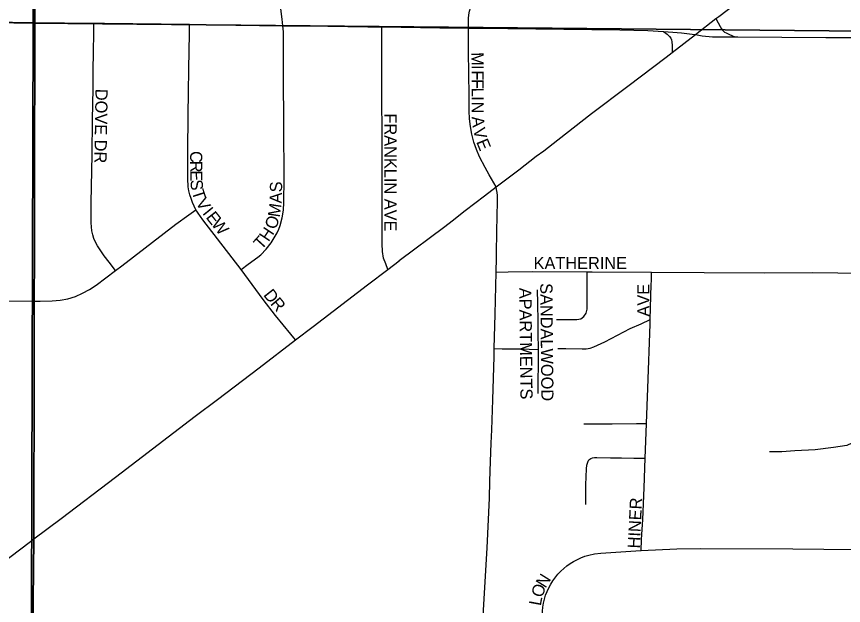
# Model space of a CAD drawing. Extents: x 1874609 to 2204689, y 815661 to 1281160.
# Drawn here: x 2012825 to 2016212, y 1038772 to 1041183 of the extents above; entities that cross this region are included whole.
import ezdxf

# ---------------------------------------------------------------- set-up
doc = ezdxf.new("R2010")
doc.units = 0
for name, color, linetype in [('GM_X_City_Street', 7, 'Continuous'), ('GM_X_City_Street_Text', 7, 'Continuous'), ('GM_X_Minor_River', 7, 'Continuous'), ('GM_X_Section', 7, 'Continuous'), ('GM_X_Township', 7, 'Continuous')]:
    doc.layers.add(name, color=color, linetype=linetype)

msp = doc.modelspace()

# ---------------------------------------------------------------- linework, layer by layer
at = {"layer": 'GM_X_City_Street'}
for points in [[(2013915.2, 1041145.8), (2013912.5, 1041172.4), (2013904.1, 1041237), (2013902.3, 1041253.9), (2013901.2, 1041272.7), (2013899.5, 1041318.9), (2013899.8, 1041467.4), (2013898.3, 1041608.2), (2013900.7, 1041634.7), (2013900.1, 1041657.5), (2013904.2, 1041695), (2013907.4, 1041727.9), (2013912.9, 1041760.4), (2013932, 1041840.3), (2013995.2, 1042077.5), (2014035.6, 1042236.1), (2014053.9, 1042301.5)], [(2014676.5, 1041135.7), (2014676.5, 1041175.8), (2014677.3, 1041190.8), (2014679.7, 1041204.9), (2014684.5, 1041219.1), (2014690.3, 1041233.7), (2014697.3, 1041247), (2014706, 1041259.7), (2014715.3, 1041273), (2014734.2, 1041299.5), (2014784.1, 1041364.7), (2014813.4, 1041404.4), (2014832.4, 1041430.6), (2014842.2, 1041443.4), (2014851.7, 1041456.1), (2014860, 1041468.7), (2014862.6, 1041474.3)], [(2015689.7, 1041174.7), (2015701.2, 1041183.5), (2016027.1, 1041431.9), (2016096.6, 1041485.7)], [(2012727.6, 1041161.3), (2012808.4, 1041160.3), (2012899.1, 1041159.1), (2012902.8, 1041159.1)], [(2012902.8, 1041159.1), (2013141.6, 1041156.1)], [(2013230.2, 1040143.5), (2013204, 1040178), (2013184.1, 1040204.2), (2013156.3, 1040244.8), (2013148, 1040259), (2013141.4, 1040274.1), (2013136.6, 1040289.8), (2013133.3, 1040305.9), (2013130.3, 1040338.7), (2013130, 1040371.5), (2013130.1, 1040420.9), (2013134.2, 1040618.4), (2013136.2, 1040759.9), (2013137.9, 1040888.3), (2013138.9, 1040958.7), (2013140, 1041041.5), (2013141, 1041111.8), (2013141.6, 1041156.1)], [(2013141.6, 1041156.1), (2013185.2, 1041155.5), (2013533.2, 1041151.5)], [(2015606.3, 1041110.1), (2015689.7, 1041174.7)], [(2015689.7, 1041174.7), (2015698.5, 1041158), (2015706.7, 1041142.6), (2015712.2, 1041133.4), (2015718.1, 1041126.6), (2015725.3, 1041119.8), (2015731.1, 1041115.9), (2015745.5, 1041109.3), (2015766.9, 1041099.7)], [(2013559.6, 1040392.5), (2013552.1, 1040406.9), (2013545.3, 1040422.2), (2013539.4, 1040437.8), (2013534.5, 1040453.8), (2013530.7, 1040470.1), (2013528, 1040486.6), (2013525.7, 1040519.8), (2013526.5, 1040634.6), (2013528.3, 1040775.6), (2013529.6, 1040877.8), (2013530.7, 1040962.2), (2013531.9, 1041048.5), (2013532.6, 1041107.3), (2013533.2, 1041151.5)], [(2013533.2, 1041151.5), (2013593.5, 1041150.8), (2013722.8, 1041148.4), (2013915.2, 1041145.8)], [(2013744.6, 1040147.1), (2013774, 1040169), (2013813, 1040198.1), (2013825.6, 1040208.3), (2013847.8, 1040231.2), (2013867.8, 1040256.4), (2013884.7, 1040283.7), (2013892.2, 1040298), (2013898.8, 1040312.5), (2013904.3, 1040327.5), (2013912.7, 1040358.5), (2013918.2, 1040390.3), (2013920, 1040422.4), (2013920.6, 1040520), (2013919.3, 1040732.5), (2013919.4, 1040797.9), (2013918.6, 1040879.5), (2013918.6, 1040934), (2013918.7, 1041006.2), (2013918.8, 1041066.1), (2013918.8, 1041098.6), (2013918.4, 1041108.8), (2013917.6, 1041121), (2013915.2, 1041145.8)], [(2013915.2, 1041145.8), (2014099.7, 1041143.2), (2014263.7, 1041141.1), (2014320.7, 1041140.4)], [(2014345.4, 1040148.3), (2014336.8, 1040170.6), (2014327.5, 1040194.4), (2014323.6, 1040220.8), (2014322.3, 1040253), (2014322.1, 1040485.1), (2014322, 1040587.2), (2014321.9, 1040689.3), (2014321.4, 1040863.6), (2014321, 1040981.5), (2014320.8, 1041054.6), (2014320.7, 1041103.7), (2014320.7, 1041140.4)], [(2014320.7, 1041140.4), (2014558.6, 1041137.4), (2014676.5, 1041135.7)], [(2014788.9, 1040485.4), (2014761.1, 1040535.2), (2014744.1, 1040565.6), (2014721.3, 1040609), (2014708.4, 1040638.8), (2014697.7, 1040669.4), (2014689.6, 1040701), (2014683.6, 1040732.9), (2014679.6, 1040765.1), (2014678.3, 1040797.7), (2014678.2, 1040879.8), (2014676.8, 1040929.1), (2014677.5, 1040945.7), (2014676.5, 1041044.2), (2014676.4, 1041110.2), (2014676.5, 1041135.7)], [(2014676.5, 1041135.7), (2014722.5, 1041135), (2015296, 1041128.3), (2015410.8, 1041125.5), (2015475.1, 1041121.7)], [(2015475.1, 1041121.7), (2015513.4, 1041118.9), (2015548.4, 1041116.2), (2015591.6, 1041111.6), (2015606.3, 1041110.1)], [(2015475.1, 1041121.7), (2015489.7, 1041111.4), (2015493.6, 1041107.5), (2015499.4, 1041102.1), (2015504.3, 1041094.7), (2015507.3, 1041087.4), (2015509.2, 1041079.5), (2015510.7, 1041064.3), (2015510.2, 1041048), (2015509.8, 1041035.5)], [(2015509.8, 1041035.5), (2015606.3, 1041110.1)], [(2015606.3, 1041110.1), (2015633.5, 1041104.8), (2015675.3, 1041100.7), (2015728.1, 1041100.1), (2015766.9, 1041099.7)], [(2015766.9, 1041099.7), (2015779.6, 1041099.6), (2016140.2, 1041097), (2016297.7, 1041097.5)], [(2014881.6, 1040556.3), (2014953.5, 1040611.2), (2014984, 1040633.5), (2015042.3, 1040679.1), (2015180.3, 1040785.6), (2015328.3, 1040898.4), (2015486.3, 1041017.2), (2015509.8, 1041035.5)], [(2014788.9, 1040485.4), (2014881.6, 1040556.3)], [(2014391.6, 1040183.1), (2014392.6, 1040183.9), (2014579.3, 1040323.9), (2014609, 1040346.9), (2014662.6, 1040388.6), (2014742, 1040449.6), (2014788.9, 1040485.4)], [(2014789.1, 1040137.4), (2014790.5, 1040195), (2014792.6, 1040321.5), (2014792.9, 1040348.6), (2014793.7, 1040373.4), (2014794.4, 1040419.2), (2014794.4, 1040450.8), (2014792.9, 1040462.8), (2014790.7, 1040475.6), (2014788.9, 1040485.4)], [(2013230.2, 1040143.5), (2013255.7, 1040162.7), (2013476.8, 1040333.5), (2013530.5, 1040371.8), (2013559.6, 1040392.5)], [(2013744.6, 1040147.1), (2013708.5, 1040195.7), (2013587.9, 1040351.2), (2013568.5, 1040378), (2013563.5, 1040386.1), (2013559.6, 1040392.5)], [(2014345.4, 1040148.3), (2014391.6, 1040183.1)], [(2012716.9, 1040020.7), (2012774, 1040019.4), (2012897.5, 1040018), (2012921.9, 1040017.7), (2012970.8, 1040019), (2013003.2, 1040021.9), (2013034.9, 1040027.6), (2013065.7, 1040037.3), (2013095.4, 1040050.1), (2013123.8, 1040065.7), (2013150.8, 1040083.8), (2013230.2, 1040143.5)], [(2013967.7, 1039859.7), (2013948.1, 1039883.6), (2013885.4, 1039959.6), (2013835.4, 1040024.8), (2013744.6, 1040147.1)], [(2013967.7, 1039859.7), (2014040, 1039914.8), (2014261.6, 1040084.9), (2014345.4, 1040148.3)], [(2014789.1, 1040137.4), (2014838.7, 1040138.2), (2014937.1, 1040139.9), (2015162.5, 1040137.9)], [(2014781.3, 1039824.8), (2014784.7, 1039965.4), (2014789.1, 1040137.4)], [(2015037.1, 1039943.3), (2015119.7, 1039943), (2015135.8, 1039945.6), (2015149.1, 1039954.8), (2015157.6, 1039968.9), (2015161.6, 1039984.9), (2015162.7, 1040001.4), (2015161.8, 1040083.8), (2015162, 1040100.3), (2015162.5, 1040137.9)], [(2015162.5, 1040137.9), (2015182.9, 1040137.8), (2015426.2, 1040136.7)], [(2015420.8, 1039942.6), (2015424.5, 1040086.8), (2015425.1, 1040103.2), (2015426.2, 1040136.7)], [(2015426.2, 1040136.7), (2015641.8, 1040135.8), (2015887.6, 1040134.2), (2016084.3, 1040134.8), (2016294.5, 1040132.5)], [(2014962.5, 1039820.1), (2014962.5, 1039828.4), (2014961.7, 1039880.6), (2014960.8, 1039934.4), (2014959.5, 1040009.1), (2014958.6, 1040064.7)], [(2015041.5, 1039823.6), (2015074.7, 1039824.2), (2015141, 1039823), (2015157.7, 1039823.4), (2015174, 1039825.8), (2015189.7, 1039830.8), (2015234.6, 1039852.2), (2015337.8, 1039905.8), (2015383.1, 1039925.9), (2015420.8, 1039942.6)], [(2015405.5, 1039517.2), (2015410.5, 1039662.5), (2015420.4, 1039923.5), (2015420.8, 1039942.6)], [(2012882.3, 1039034.5), (2012896, 1039044.8), (2013007.7, 1039127.9), (2013230.1, 1039297.1), (2013555.9, 1039547.3), (2013647.8, 1039616), (2013818, 1039745.5), (2013967.7, 1039859.7)], [(2014726.9, 1038525.3), (2014728.4, 1038550), (2014736.6, 1038730.4), (2014753.1, 1039008.3), (2014761.4, 1039211.9), (2014763.8, 1039281.3), (2014766.6, 1039362.1), (2014769.2, 1039436.8), (2014771.1, 1039491.5), (2014775.3, 1039613.9), (2014780.6, 1039791.1), (2014781.3, 1039824.8)], [(2014781.3, 1039824.8), (2014813.5, 1039823.2), (2014829.6, 1039822.5), (2014893.4, 1039822.6), (2014924.2, 1039821.4), (2014962.5, 1039820.1)], [(2014961, 1039640), (2014961.1, 1039688.5), (2014962.6, 1039760.7), (2014962.5, 1039798), (2014962.5, 1039820.1)], [(2015148.7, 1039515.7), (2015264.7, 1039516.1), (2015363.8, 1039516.9), (2015405.5, 1039517.2)], [(2015400.3, 1039375.3), (2015405.4, 1039515.6), (2015405.5, 1039517.2)], [(2015156.7, 1039185.9), (2015156.2, 1039218.2), (2015156.9, 1039266.5), (2015158.8, 1039331.1), (2015160.4, 1039347.3), (2015165.7, 1039362.4), (2015169.3, 1039368), (2015176.6, 1039373.6), (2015183.8, 1039376.7), (2015192.1, 1039378.1), (2015201.9, 1039378.6), (2015257.2, 1039377.1), (2015302.4, 1039376.4), (2015353.1, 1039375.6), (2015400.3, 1039375.3)], [(2015382.7, 1038997), (2015385.3, 1039042.6), (2015390, 1039124.1), (2015396, 1039254.5), (2015400.3, 1039375.3)], [(2012759.3, 1038943.2), (2012796.8, 1038970.6), (2012882.3, 1039034.5)], [(2014975.9, 1038522.2), (2014976.3, 1038568.6), (2014977.5, 1038732.4), (2014980.2, 1038765.6), (2014983, 1038782), (2014986.8, 1038798.3), (2014991.7, 1038814.3), (2014997.7, 1038829.9), (2015004.9, 1038845), (2015013, 1038859.6), (2015022.1, 1038873.6), (2015042.5, 1038900), (2015053.7, 1038912.3), (2015065.9, 1038923.8), (2015078.8, 1038934.5), (2015092.4, 1038944.2), (2015106.7, 1038952.9), (2015136.7, 1038967.5), (2015152.3, 1038973.6), (2015168.3, 1038978.5), (2015191.7, 1038983.7), (2015217.7, 1038986.4), (2015381.5, 1038996.9), (2015382.7, 1038997)], [(2015382.7, 1038997), (2015529, 1039003.9), (2015627.6, 1039005.8), (2016004.9, 1039003.7), (2016386.7, 1039000.3)]]:
    msp.add_lwpolyline(points, dxfattribs=at)
at = {"layer": 'GM_X_Minor_River'}
msp.add_lwpolyline([(2016625.8, 1039650.1), (2016575.6, 1039646.3), (2016503.3, 1039624.4), (2016416.9, 1039572.6), (2016352.6, 1039522.6), (2016282.2, 1039452.7), (2016225.9, 1039426.8), (2016171.8, 1039418.9), (2016095.5, 1039409.2), (2016013.3, 1039405.4), (2015959.1, 1039401.6), (2015909, 1039401.8)], dxfattribs=at)
at = {"layer": 'GM_X_Section'}
for points in [[(2012915.3, 1046513.3), (2012892.7, 1041156.5), (2007599.8, 1041247.3), (2007626.4, 1046598.1)], [(2019020.7, 1046448.2), (2018988, 1041097.3), (2012892.7, 1041156.5), (2012915.3, 1046513.3)], [(2007599.8, 1041247.3), (2012892.7, 1041156.5), (2012877.9, 1035897.7), (2011531.4, 1035800.8), (2010681, 1035777), (2010086.6, 1035805.8), (2009320.1, 1035878.2), (2007577.2, 1035888.5)], [(2012892.7, 1041156.5), (2018988, 1041097.3), (2018912.9, 1035910.5), (2012877.9, 1035897.7)]]:
    msp.add_lwpolyline(points, close=True, dxfattribs=at)
at = {"layer": 'GM_X_Township'}
for points in [[(2012924.9, 1056002.2), (2012935.3, 1053679.3), (2012914.5, 1051827.7), (2012910.2, 1048822.6), (2012903.7, 1044302.1), (2012899.1, 1041173.4), (2012896.1, 1039044.8), (2012861.2, 1035880.2), (2012864.4, 1032937.1), (2012859.2, 1032479.4), (2012845.9, 1030538.4), (2012837.6, 1027645.9), (2012830.6, 1025241.9), (2010175.8, 1025275.6)], [(2037504.4, 1025002.2), (2030477.9, 1025070.5), (2023338.3, 1025139.8), (2019554.9, 1025176.6), (2018880.2, 1025183.1), (2014559, 1025225.1), (2013359, 1025236.7), (2012830.6, 1025241.9), (2012837.6, 1027645.9), (2012845.9, 1030538.4), (2012859.2, 1032479.4), (2012864.4, 1032937.1), (2012861.2, 1035880.2), (2012896.1, 1039044.8), (2012899.1, 1041173.4), (2012903.7, 1044302.1), (2012910.2, 1048822.6), (2012914.5, 1051827.7), (2012935.3, 1053679.3), (2012924.9, 1056002.2)]]:
    msp.add_lwpolyline(points, dxfattribs=at)

# ---------------------------------------------------------------- texts
at = {"layer": 'GM_X_City_Street_Text'}
for s, rotation, p in [('M', 270.1457, (2014688.2, 1041037.3)), ('I', 270.1504, (2014688.3, 1040984.5)), ('F', 270.1366, (2014688.4, 1040962.5)), ('F', 270.1588, (2014688.4, 1040927.3)), ('L', 270.1366, (2014688.5, 1040892.1)), ('DOVE DR', 269.0613, (2013148.2, 1040887.6)), ('I', 270.1504, (2014688.6, 1040856.9)), ('N', 270.153, (2014688.7, 1040834.9)), ('FRANKLIN AVE', 270, (2014331.8, 1040786.5)), ('A', 275.6868, (2014689.1, 1040772.4)), ('V', 282.3494, (2014694.5, 1040722.3)), ('E', 292.2306, (2014706.7, 1040670.4)), ('C', 270.4129, (2013535.4, 1040632.4)), ('R', 270.4097, (2013535.6, 1040592.8)), ('E', 270.4219, (2013535.9, 1040553.2)), ('S', 274.4437, (2013536.4, 1040514.2)), ('T', 287.9175, (2013541.6, 1040466.5)), ('S', 89.8823, (2013912.5, 1040463.5)), ('V', 300.3699, (2013557.2, 1040422.2)), ('A', 88.0562, (2013910.9, 1040417.8)), ('M', 81.5097, (2013902.6, 1040359.4)), ('I', 308.9859, (2013584.1, 1040377.6)), ('E', 308.3398, (2013597.9, 1040360.6)), ('W', 308.4089, (2013619.8, 1040332.9)), ('O', 72.5403, (2013887.5, 1040309.1)), ('H', 56.4498, (2013856.6, 1040258.6)), ('T', 47.6859, (2013827.7, 1040226)), ('KATHERINE', 0, (2014942.8, 1040149.1)), ('APARTMENTS', 270.6214, (2014883.8, 1040072.7)), ('SANDALWOOD', 270.561, (2014969.8, 1040091.5)), ('AVE', 90, (2015417.4, 1039954.9)), ('D', 308.2161, (2013833.6, 1040042.9)), ('R', 310.123, (2013861.9, 1040006.9)), ('HINER', 87.27, (2015377.8, 1039005)), ('N', 58.0317, (2014990.9, 1038840.4)), ('O', 71.1711, (2014978, 1038801.5)), ('L', 79.4777, (2014972.1, 1038768.7))]:
    msp.add_text(s, height=50, rotation=rotation, dxfattribs=at).set_placement(p)

doc.saveas('drawing.dxf')
